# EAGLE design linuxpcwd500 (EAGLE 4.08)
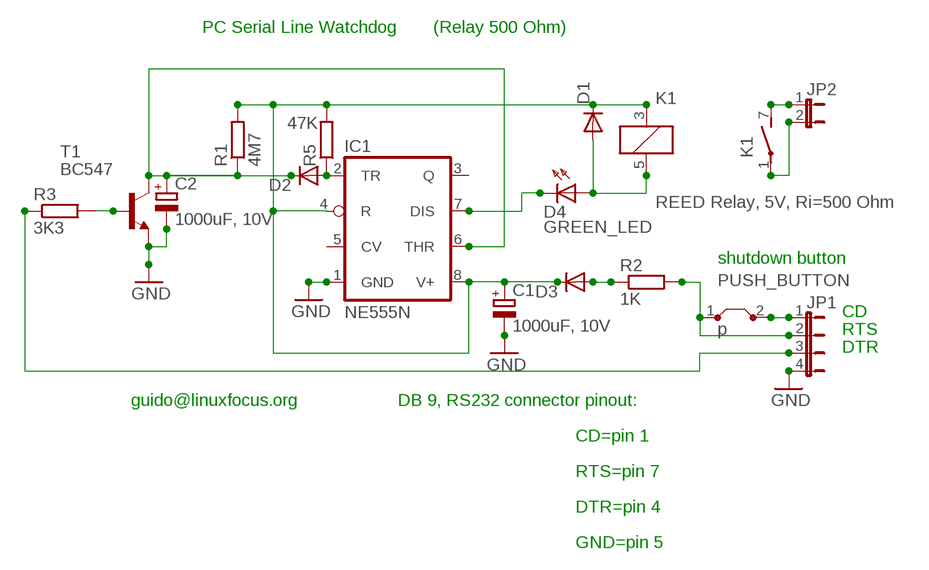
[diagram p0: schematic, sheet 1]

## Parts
C1  1000uF, 10V  CPOL-EUE3.5-10  [E3,5-10]
C2  1000uF, 10V  CPOL-EUE3.5-10  [E3,5-10]
D1  DIODE-D-5  [D-5]
D2  DIODE-D-7.5  [D-7.5]
D3  DIODE-D-5  [D-5]
D4  GREEN_LED  LED3MM  [LED3MM]
IC1  NE555N  [DIL08]
JP1  JP4E  [JP4]
JP2  JP1E  [JP1]
K1  REED Relay, 5V, Ri=500 Ohm  REED  [REED]
PUSH_BUTTON  p  J5MM  [05]
R1  4M7  R-EU_0204/5  [0204/5]
R2  1K  R-EU_0204/5  [0204/5]
R3  3K3  R-EU_0204/5  [0204/5]
R5  47K  R-EU_0204/7  [0204/7]
T1  BC547  [TO92]

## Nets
GND: C1.- C2.- IC1.1(GND) JP1.4 T1.1(E)
N$2: D2.A IC1.2(TR) R5.1
N$3: C2.+ D2.C IC1.6(THR) R1.1 T1.3(C)
N$5: R3.2 T1.2(B)
N$6: D3.A R2.1
N$8: JP2.1 K1.7(2:S)
N$9: D1.A D4.A K1.5(1:-)
N$10: JP2.2 K1.1(2:P)
N$11: D4.K(C) IC1.7(DIS)
N$13: JP1.1 PUSH_BUTTON.2
N$14: JP1.2 PUSH_BUTTON.1 R2.2
N$15: JP1.3 R3.1
V+: C1.+ D1.C D3.C IC1.4(R) IC1.8(V+) K1.3(1:+) R1.2 R5.2
Unconnected: IC1.3(Q) IC1.5(CV)

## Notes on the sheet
- PC Serial Line Watchdog | (Relay 500 Ohm)
- shutdown button
- CD
- RTS
- DTR
- guido@linuxfocus.org | DB 9, RS232 connector pinout:
- CD=pin 1
- RTS=pin 7
- DTR=pin 4
- GND=pin 5

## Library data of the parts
C1 C2 = rclgus:CPOL-EU: POLARIZED CAPACITOR, European symbol
D1-D3 = diode:DIODE-: DIODE
D4 = led:LED3MM: LED
IC1 = linear:*555: TIMER
JP1 = jumper:JP4E: JUMPER
JP2 = jumper:JP1E: JUMPER
K1 = relay:REED: RELAY reed, 1 x norm. open with polarity, grid 5.08
PUSH_BUTTON = jumper:J: Bridge
R1-R3 R5 = rclgus:R-EU_: RESISTOR, European symbol
T1 = transistor-npn:BC547: NPN TRANSISTOR

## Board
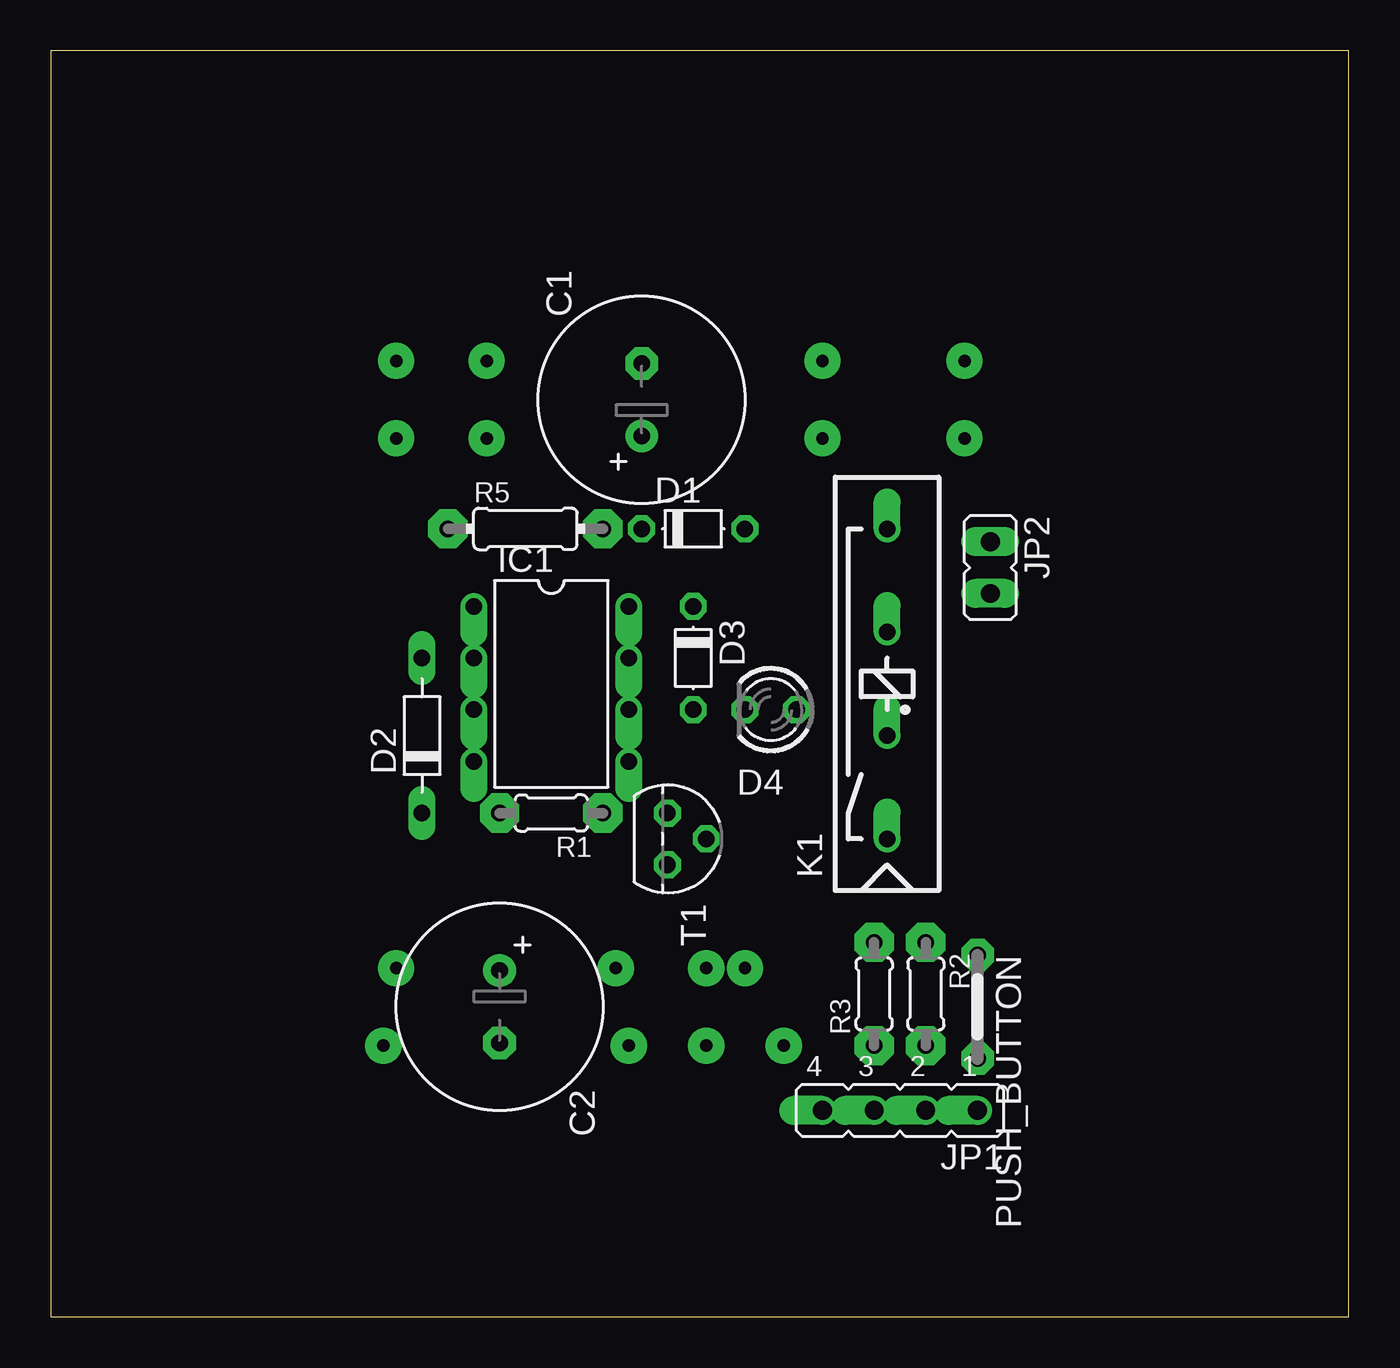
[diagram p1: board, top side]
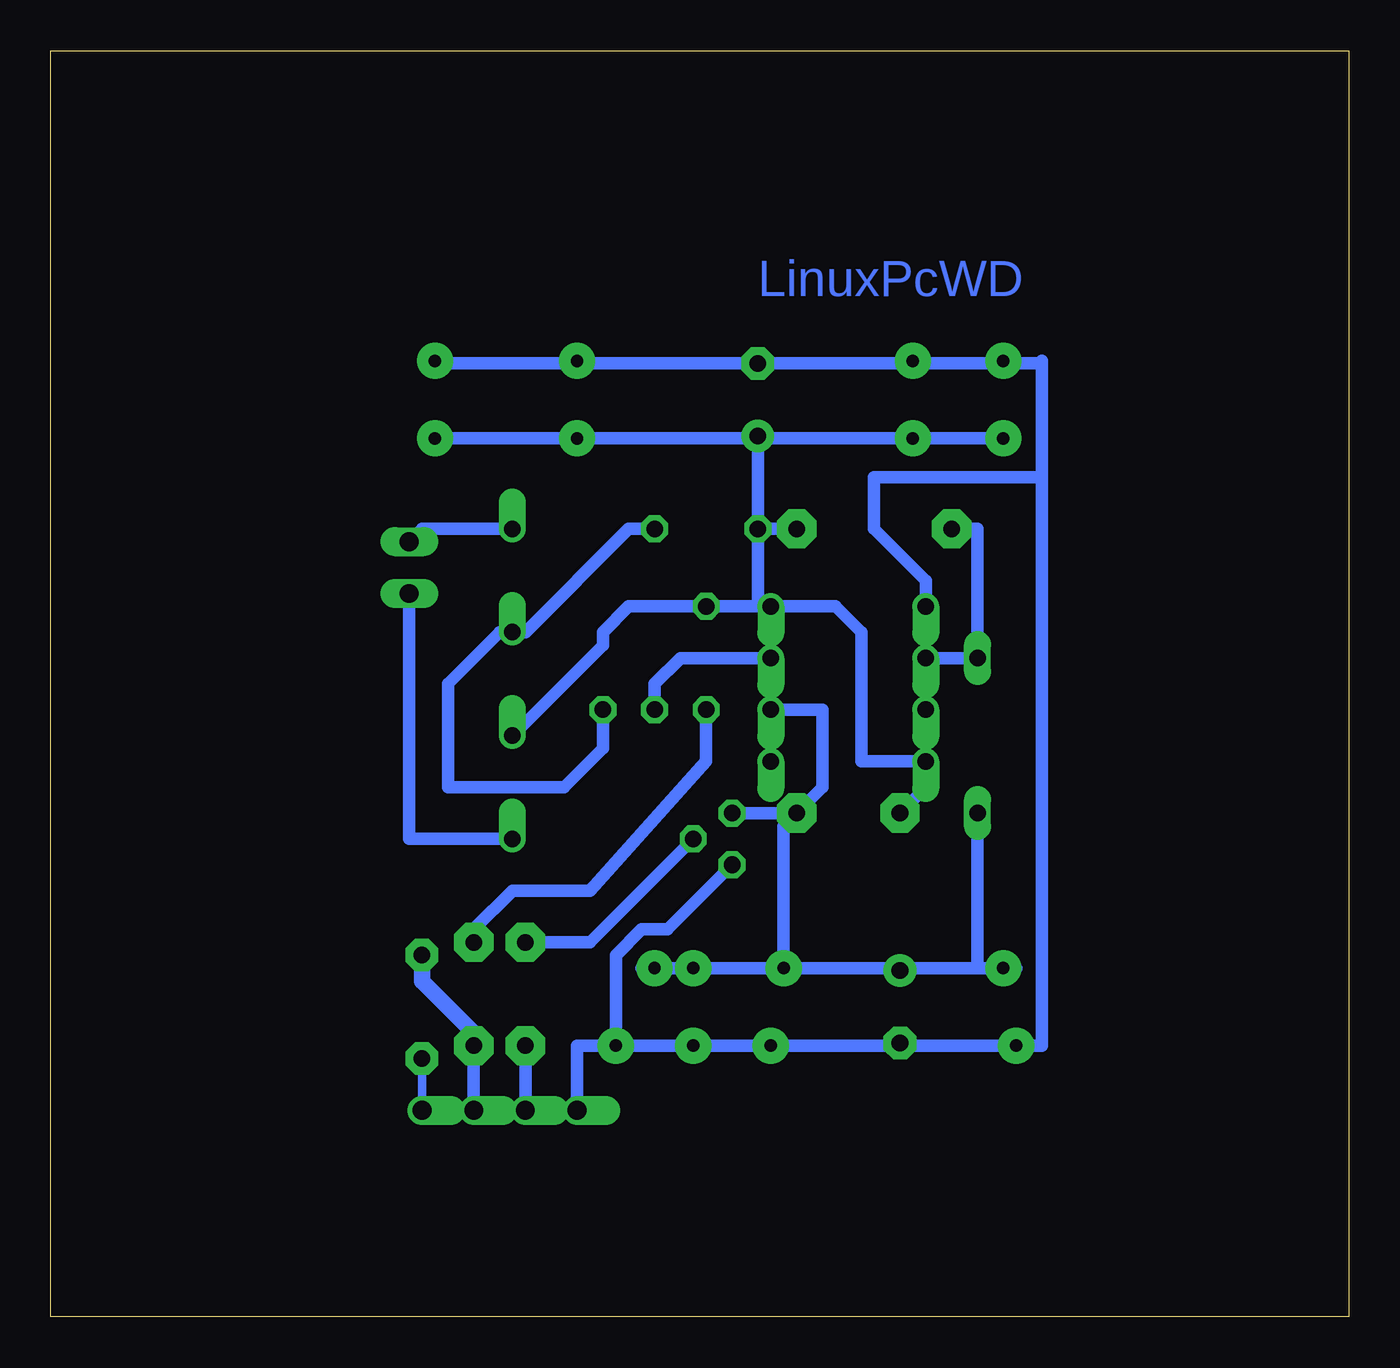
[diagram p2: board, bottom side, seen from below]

Size 63.8 x 62.22 mm. Coordinates in mm from the lower left corner, seen from the top.
Outline: 0,0 63.8,0 63.8,62.22 0,62.22 0,0
Copper layers used: Top, Bottom

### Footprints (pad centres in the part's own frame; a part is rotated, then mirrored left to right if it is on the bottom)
E3,5-10 = drill 0.813 pad 1.6 round: + -1.778,0 | drill 0.813 pad 1.6 octagon: - 1.778,0
D-5 = drill 0.813 octagon: A 2.54,0; C -2.54,0
D-7.5 = drill 0.813 long: A 3.81,0; C -3.81,0
LED3MM = drill 0.813 octagon: A -1.27,0; K 1.27,0
DIL08 = drill 0.813 offset: 1 -3.81,-3.81; 2 -1.27,-3.81; 3 1.27,-3.81; 4 3.81,-3.81; 5 3.81,3.81; 6 1.27,3.81; 7 -1.27,3.81; 8 -3.81,3.81
JP4 = drill 0.914 offset: 1 -3.81,0; 2 -1.27,0; 3 1.27,0; 4 3.81,0
JP1 = drill 0.914 long: 1 0,-1.27; 2 0,1.27
REED = drill 0.813 offset: 1 -17.78,2.54; 3 -12.7,2.54; 5 -7.62,2.54; 7 -2.54,2.54
05 = drill 0.813 pad 1.6 octagon: 1 -2.54,0; 2 2.54,0
0204/5 = drill 0.813 pad 1.93 octagon: 1 -2.54,0; 2 2.54,0
0204/7 = drill 0.813 pad 1.93 octagon: 1 -3.81,0; 2 3.81,0
TO92 = drill 0.813 octagon: 1 1.27,0; 2 0,1.905; 3 -1.27,0

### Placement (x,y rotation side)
C1  29.05,45.08 90 top
C2  22.06,15.23 270 top
D1  31.59,38.73 0 top
D2  18.25,28.57 90 top
D3  31.59,32.38 270 top
D4  35.4,29.84 180 top
IC1  24.6,31.11 270 top
JP1  41.75,10.16 180 top
JP2  46.19,36.83 180 top
K1  43.65,41.27 90 top
PUSH_BUTTON  45.55,15.23 270 top
R1  24.6,24.76 180 top
R2  43.02,15.87 270 top
R3  40.48,15.87 90 top
R5  23.33,38.73 0 top
T1  30.32,23.49 270 top

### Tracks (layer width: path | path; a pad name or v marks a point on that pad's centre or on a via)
GND  (via drill 0.61 pad 1.78)
  Bottom 0.254: 21.43,13.33 C2.- | 21.43,13.33
  Bottom 0.61: 15.2,46.86 C1.- | 15.2,46.86 15.08,46.98 15.08,41.27 | 15.08,41.27 15.08,13.33 v16.34,13.33 21.43,13.33 v28.41,13.33 v32.22,13.33 v36.03,13.33 | v36.03,13.33 37.94,13.33 JP1.4 | 15.2,46.86 44.79,46.86 v44.92,46.98 | IC1.1 20.79,36.19 23.33,38.73 23.33,41.27 15.08,41.27 | T1.1 33.49,19.04 34.76,19.04 36.03,17.77 v36.03,13.33
N$1  (via drill 0.61 pad 1.78)
  other vias: 16.98,46.98
N$2
  Bottom 0.61: IC1.2 D2.A 18.25,38.73 R5.1
N$3  (via drill 0.61 pad 1.78)
  Bottom 0.254: 21.43,17.14 C2.+ | 21.43,17.14
  Bottom 0.61: R1.1 T1.3 | IC1.6 25.87,29.84 25.87,26.03 R1.1 | 18.25,17.14 D2.C | 18.25,17.14 v16.98,17.14 16.34,17.14 | 18.25,17.14 21.43,17.14 v27.77,17.14 | v27.77,17.14 v32.22,17.14 v34.12,17.14 34.76,17.14 | v27.77,17.14 27.77,24.12 R1.1
N$4  (via drill 0.61 pad 1.78)
  other vias: 37.94,46.98
N$5
  Bottom 0.61: T1.2 37.3,18.41 R3.2
N$6
  Bottom 0.61: D3.A 31.59,27.3 37.3,20.95 41.11,20.95 43.02,19.04 R2.1
N$7  (via drill 0.61 pad 1.78)
  other vias: 21.43,46.98
N$8
  Bottom 0.61: K1.7 45.55,38.73 JP2.1
N$9
  Bottom 0.61: D4.A 36.66,27.94 38.57,26.03 44.29,26.03 44.29,31.11 41.75,33.65 K1.5 40.48,33.65 35.4,38.73 D1.A
N$10
  Bottom 0.61: JP2.2 46.19,23.49 K1.1
N$11
  Bottom 0.61: IC1.7 32.86,32.38 34.12,31.11 D4.K
N$13
  Bottom 0.406: JP1.1 PUSH_BUTTON.2
N$14  (via drill 0.61 pad 1.78)
  Top 0.254: R2.2
  Bottom 0.61: JP1.2 R2.2
  Bottom 0.813: R2.2 43.02,13.96 45.55,16.5 PUSH_BUTTON.1
  other vias: 43.01,13.33
N$15
  Bottom 0.61: JP1.3 R3.1
V+  (via drill 0.61 pad 1.78)
  Bottom 0.61: D1.C R5.2 | 29.05,34.92 IC1.8 25.23,34.92 23.97,33.65 23.97,27.3 IC1.4 20.79,26.03 R1.2 | 29.05,34.92 D1.C | 29.05,34.92 D3.C 35.4,34.92 36.66,33.65 36.66,33.02 K1.3 | 29.05,43.17 C1.+ | D1.C 29.05,43.17 | 29.05,43.17 v21.43,43.17 v16.98,43.17 | v44.92,43.17 v37.94,43.17 29.05,43.17

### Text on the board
Bottom: LinuxPcWD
